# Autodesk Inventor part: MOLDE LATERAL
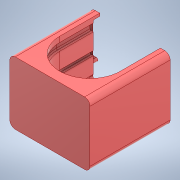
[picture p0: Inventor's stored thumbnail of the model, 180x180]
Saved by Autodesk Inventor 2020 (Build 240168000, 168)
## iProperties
Created: 2022-09
Part Number: MOLDE LATERAL
Material: PVC, no plastificado
Document SubType Name: Modeling
Designer: SEBAS
Density: 1.29 g/cm^3
Appearance: Suave - Rojo
Author: SEBAS
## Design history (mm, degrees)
sketch "Boceto3"
  geometry: L1 (36, 58)-(36, 0); L2 (36, 0)-(26, 0); L3 (26, 0)-(26, 5); L4 (26, 5)-(31, 5); L5 (31, 5)-(31, 12); L6 (31, 12)-(26, 12); L7 (26, 12)-(26, 27); L8 (26, 27)-(31, 27); L9 (31, 27)-(31, 31); L10 (31, 31)-(26, 31); L11 (26, 31)-(26, 46); L12 (26, 46)-(31, 46); L13 (31, 46)-(31, 53); L14 (31, 53)-(26, 53); L15 (26, 53)-(26, 58); L16 (26, 58)-(36, 58); L17 (0, 0)-(0, 55); L18 (26, 5)-(26, 12); L19 (26, 27)-(26, 31); L20 (26, 53)-(26, 46); L21 (31, 53)-(31, 58); L22 (31, 5)-(31, 0); L23 (-26, 58)-(-28, 58); L24 (-28, 58)-(-28, 0); L25 (-28, 0)-(-26, 0); L26 (-26, 0)-(-26, 58)
  constraints: 52 end point, 11 perpendicular, 8 point on line, 5 collinear, 4 horizontal alignment, 3 vertical, 2 horizontal, 2 midpoint, 2 parallel, 1 vertical alignment
  dimensions: "d27" = 31 distance from line of L17.start L5; "d28" = 10 distance of L1.end L2.end; "d29" = 5 distance of L4.end L3.end; "d30" = 5 distance of L14.end L15.end; "d33" = 4 distance of L8.end L9.end; "d34" = 15 distance of L10.end L11.end; "d35" = 7 distance of L4.end L5.end; "d78" = 2 distance between parallel lines of L24 L26; "d79" = 28 distance of L24.end L17.start
sketch "Boceto4"
  geometry: L1 (0, -13.5)-(0, 13.5); L2 (37, 37)-(-37, 37); L3 (-37, 37)-(-37, -37); L4 (-37, -37)-(37, -37); L5 (37, -37)-(37, 37); L6 (37, 37)-(-37, -37); L7 (-37, 37)-(37, -37); L8 (-27, 27)-(27, 27); L9 (27, 27)-(27, -27); L10 (27, -27)-(-27, -27); L11 (-27, -27)-(-27, 27); L12 (-27, 27)-(27, -27); L13 (27, 27)-(-27, -27); L14 (37, 0)-(-37, 0); 4 further points
  constraints: 28 end point, 7 midpoint, 4 parallel, 4 perpendicular, 2 horizontal, 1 coincident
  dimensions: "d38" = 37 horizontal distance of L2.end point (0, 0); "d39" = 10 distance between parallel lines of L2 L8
revolve "Revolución2" stored, may be unused: angle "d40" = 180 deg
extrude "Extrusión2" join sketch "Boceto4" stored distance "d41" = 10; taper "d42" = 0 deg
revolve "Revolución3" stored, may be unused: angle "d43" = 90 deg
fillet "Empalme2" dims "d44" = 5
sketch "Boceto6"
  geometry: L1 (31, 31)-(-31, 31) reference; L2 (31, 27)-(31, 31) reference; L3 (31, 27)-(-31, 27) reference; L4 (-31, 31)-(-31, 27) reference; L5 (31, 29)-(-31, 29); L6 (-31, 31)-(-31, 27) reference; L7 (12.5, 16.5)-(-12.5, 16.5); L8 (-12.5, 16.5)-(-12.5, 41.5); L9 (-12.5, 41.5)-(12.5, 41.5); L10 (12.5, 41.5)-(12.5, 16.5); L11 (12.5, 16.5)-(-12.5, 41.5); L12 (-12.5, 16.5)-(12.5, 41.5); 2 further points
  constraints: 14 end point, 5 midpoint, 2 parallel, 2 perpendicular, 1 horizontal
  dimensions: "d53" = 25 distance of L8.end L9.end
extrude "Extrusión5" cut sketch "Boceto6" distance "d54" = 33; taper "d55" = 0 deg
sketch "Boceto11"
  geometry: L1 (5, -10)-(5, -13.188) reference; L2 (8.188, -10)-(5, -10) reference; L3 (59, -13.188)-(59, -10) reference; L4 (59, -10)-(55.812, -10) reference; A1 r 36 centre (32, -37) between (8.188, -10) and (5, -13.188) reference; A2 r 36 centre (32, -37) between (59, -13.188) and (55.812, -10) reference; 1 further point
extrude "Extrusión10" join sketch "Boceto11" stored distance "d74" = 30; taper "d75" = 0 deg
revolve "Revolución5" stored, may be unused: angle "d80" = 90 deg
sketch "Boceto12"
  geometry: L1 (3, 48)-(3, 53) reference; L2 (3, 53)-(-1, 53) reference; L3 (-6, 0)-(-6, 48) reference; L4 (3, -5)-(-1, -5) reference; L5 (3, -5)-(3, 0) reference; L6 (0, 0)-(3, 0) reference; L7 (0, 0)-(0, 7) reference; L8 (3, 7)-(0, 7) reference; L9 (3, 7)-(3, 22) reference; L10 (0, 22)-(3, 22) reference; L11 (0, 22)-(0, 26) reference; L12 (3, 26)-(0, 26) reference; L13 (3, 26)-(3, 41) reference; L14 (0, 41)-(3, 41) reference; L15 (0, 41)-(0, 48) reference; L16 (3, 48)-(0, 48) reference; L17 (59, 53)-(59, 48) reference; L18 (59, 48)-(62, 48) reference; L19 (62, 48)-(62, 41) reference; L20 (62, 41)-(59, 41) reference; L21 (59, 41)-(59, 26) reference; L22 (59, 26)-(62, 26) reference; L23 (62, 26)-(62, 22) reference; L24 (62, 22)-(59, 22) reference; L25 (59, 22)-(59, 7) reference; L26 (59, 7)-(62, 7) reference; L27 (62, 7)-(62, 0) reference; L28 (62, 0)-(59, 0) reference; L29 (59, 0)-(59, -5) reference; L30 (59, -5)-(63, -5) reference; L31 (68, 0)-(68, 48) reference; L32 (63, 53)-(59, 53) reference; A1 r 5 centre (-1, 48) between (-1, 53) and (-6, 48) reference; A2 r 5 centre (-1, 0) between (-6, 0) and (-1, -5) reference; A3 r 5 centre (63, 0) between (63, -5) and (68, 0) reference; A4 r 5 centre (63, 48) between (68, 48) and (63, 53) reference; 1 further point
extrude "Extrusión12" join sketch "Boceto12" distance "d81" = 37; taper "d82" = 0 deg
fillet "Empalme11" dims "d83" = 1
fillet "Empalme12" dims "d84" = 2
sketch "Boceto13"
  geometry: L1 (3, -5)-(3, 0) reference; L2 (3, 0)-(1, 0) reference; L3 (0, 1)-(0, 6) reference; L4 (1, 7)-(3, 7) reference; L5 (3, 7)-(3, 22) reference; L6 (3, 22)-(1, 22) reference; L7 (0, 23)-(0, 25) reference; L8 (1, 26)-(3, 26) reference; L9 (3, 26)-(3, 41) reference; L10 (3, 41)-(1, 41) reference; L11 (0, 42)-(0, 47) reference; L12 (1, 48)-(3, 48) reference; L13 (3, 48)-(3, 53) reference; L14 (3, 53)-(-1, 53) reference; L15 (-6, 48)-(-6, 0) reference; L16 (-1, -5)-(3, -5) reference; L17 (68, 0)-(68, 48) reference; L18 (63, 53)-(59, 53) reference; L19 (59, 53)-(59, 48) reference; L20 (59, 48)-(61, 48) reference; L21 (62, 47)-(62, 42) reference; L22 (61, 41)-(59, 41) reference; L23 (59, 41)-(59, 26) reference; L24 (59, 26)-(61, 26) reference; L25 (62, 25)-(62, 23) reference; L26 (61, 22)-(59, 22) reference; L27 (59, 22)-(59, 7) reference; L28 (59, 7)-(61, 7) reference; L29 (62, 6)-(62, 1) reference; L30 (61, 0)-(59, 0) reference; L31 (59, 0)-(59, -5) reference; L32 (59, -5)-(63, -5) reference; L33 (3, 48)-(3, 53) reference; L34 (3, 50.5)-(-1, 50.5); L35 (-3.5, 48)-(-3.5, 0); L36 (-1, -2.5)-(3, -2.5); L37 (3, -5)-(3, 0) reference; L38 (3, 26)-(3, 41) reference; L39 (3, 33.5)-(-3.5, 33.5); L40 (3, 14.5)-(-3.5, 14.5); L41 (-3.5, 48)-(-1, 48); L42 (-1, 48)-(-1, 50.5); L43 (-3.5, 0)-(-1, 0); L44 (-1, 0)-(-1, -2.5); L45 (3, 50.5)-(3, -2.5); L46 (31, -5)-(31, 53); L47 (3, 53)-(59, 53) reference; L48 (65.5, 48)-(65.5, 0); L49 (59, 50.5)-(63, 50.5); L50 (59, 50.5)-(59, -2.5); L51 (63, -2.5)-(59, -2.5); L52 (-0.25, 35)-(-3.5, 35); L53 (-0.25, 32)-(-3.5, 32); L54 (62.25, 16)-(65.5, 16); L55 (62.25, 13)-(65.5, 13); C1 r 1.5 at (-0.25, 14.5); C2 r 1.5 at (62.25, 33.5); A1 r 1 centre (1, 1) between (0, 1) and (1, 0) reference; A2 r 1 centre (1, 6) between (1, 7) and (0, 6) reference; A3 r 1 centre (1, 23) between (0, 23) and (1, 22) reference; A4 r 1 centre (1, 25) between (1, 26) and (0, 25) reference; A5 r 1 centre (1, 42) between (0, 42) and (1, 41) reference; A6 r 1 centre (1, 47) between (1, 48) and (0, 47) reference; A7 r 5 centre (-1, 48) between (-1, 53) and (-6, 48) reference; A8 r 5 centre (-1, 0) between (-6, 0) and (-1, -5) reference; A9 r 5 centre (63, 48) between (68, 48) and (63, 53) reference; A10 r 1 centre (61, 47) between (62, 47) and (61, 48) reference; A11 r 1 centre (61, 42) between (61, 41) and (62, 42) reference; A12 r 1 centre (61, 25) between (62, 25) and (61, 26) reference; A13 r 1 centre (61, 23) between (61, 22) and (62, 23) reference; A14 r 1 centre (61, 6) between (62, 6) and (61, 7) reference; A15 r 1 centre (61, 1) between (61, 0) and (62, 1) reference; A16 r 5 centre (63, 0) between (63, -5) and (68, 0) reference; A17 r 2.5 centre (-1, 0) between (-3.5, 0) and (-1, -2.5); A18 r 2.5 centre (-1, 48) between (-1, 50.5) and (-3.5, 48); A19 r 1.5 centre (-0.25, 33.5) between (-0.25, 35) and (-0.25, 32); A20 r 2.5 centre (63, 48) between (65.5, 48) and (63, 50.5); A21 r 2.5 centre (63, 0) between (63, -2.5) and (65.5, 0); A22 r 1.5 centre (62.25, 14.5) between (62.25, 16) and (62.25, 13); 4 further points
  constraints: 38 end point, 14 point on circle, 11 symmetric about line, 8 centre point, 7 midpoint, 7 perpendicular, 7 tangent, 6 point on line, 4 horizontal, 2 coincident, 2 vertical, 1 equal radius, 4 other
  dimensions: "d85" = 3 diameter of C1
  node "Contorno proyectado11"
  node "Contorno proyectado12"
extrude "Extrusión13" cut sketch "Boceto13" distance "d86" = 6; taper "d87" = 0 deg
extrude "Extrusión14" cut sketch "Boceto13" distance "d88" = 20; taper "d89" = 0 deg
fillet "Empalme13" dims "d90" = 1
extrude "Extrusión15" join sketch "Boceto13" distance "d91" = 6; taper "d92" = 0 deg
fillet "Empalme14" dims "d93" = 1
node "Sólido2"
node "Contorno proyectado3"
node "Contorno proyectado9"
node "Contorno proyectado10"
